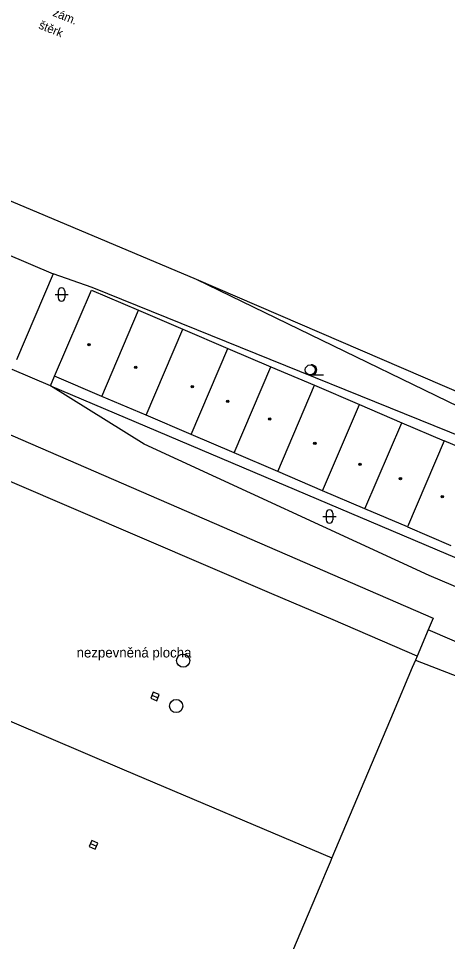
# Model space of a CAD drawing. Extents: x -596024 to -594475, y -1163820 to -1161957.
# Drawn here: x -594771.3 to -594738.8, y -1162292 to -1162222 of the extents above; entities that cross this region are included whole.
import ezdxf

# ---------------------------------------------------------------- set-up
doc = ezdxf.new("R2010")
doc.units = 0
for name, color, linetype in [('Level 10', 7, 'Continuous'), ('Level 11', 7, 'Continuous'), ('Level 14', 7, 'Continuous'), ('Level 27', 7, 'Continuous'), ('Level 36', 7, 'Continuous'), ('Level 39', 7, 'Continuous'), ('Level 40', 7, 'Continuous'), ('Level 42', 7, 'Continuous'), ('Level 5', 7, 'Continuous'), ('Level 6', 7, 'Continuous'), ('Level 7', 7, 'Continuous')]:
    doc.layers.add(name, color=color, linetype=linetype)

msp = doc.modelspace()

# ---------------------------------------------------------------- linework, layer by layer
at = {"layer": 'Level 10'}
for points in [[(-594783.33, -1162270.4), (-594763.33, -1162278.94)], [(-594763.33, -1162278.94), (-594747.59, -1162285.62)]]:
    msp.add_lwpolyline(points, dxfattribs=at)
at = {"layer": 'Level 11'}
for points in [[(-594768.91, -1162249.85), (-594771.8, -1162248.61)], [(-594768.91, -1162249.85), (-594768.6, -1162249.12)], [(-594717.37, -1162273.91), (-594740.22, -1162264.21), (-594761.82, -1162254.28), (-594768.91, -1162249.85)], [(-594768.91, -1162249.85), (-594715.49, -1162272.51)], [(-594752.13, -1162265.61), (-594776.82, -1162255.03)], [(-594747.5, -1162267.57), (-594752.13, -1162265.61)], [(-594741.13, -1162270.32), (-594747.5, -1162267.57)], [(-594718.87, -1162277.56), (-594740.29, -1162268.33)]]:
    msp.add_lwpolyline(points, dxfattribs=at)
at = {"layer": 'Level 14'}
for points in [[(-594765.75, -1162242.39), (-594768.7, -1162241.36)], [(-594729.66, -1162257), (-594765.75, -1162242.39)], [(-594729.32, -1162255.62), (-594757.85, -1162241.8)]]:
    msp.add_lwpolyline(points, dxfattribs=at)
at = {"layer": 'Level 27'}
for p, q in [((-594761.22, -1162273.283), (-594760.76, -1162273.477)), ((-594765.869, -1162284.53), (-594765.411, -1162284.73))]:
    msp.add_line(p, q, dxfattribs=at)
for points in [[(-594761.317, -1162273.513), (-594760.857, -1162273.707), (-594760.663, -1162273.247), (-594761.123, -1162273.053)], [(-594765.969, -1162284.759), (-594765.511, -1162284.959), (-594765.311, -1162284.501), (-594765.769, -1162284.301)]]:
    msp.add_lwpolyline(points, close=True, dxfattribs=at)
for centre in [(-594758.85, -1162270.67), (-594759.39, -1162274.11)]:
    msp.add_circle(centre, 0.5, dxfattribs=at)
at = {"layer": 'Level 36'}
for p, q in [((-594768.566, -1162242.936), (-594767.566, -1162242.936)), ((-594768.316, -1162242.686), (-594768.316, -1162243.186)), ((-594767.816, -1162242.686), (-594767.816, -1162243.186)), ((-594749.23, -1162249.015), (-594748.23, -1162249.015)), ((-594748.266, -1162259.746), (-594747.266, -1162259.746)), ((-594748.016, -1162259.496), (-594748.016, -1162259.996)), ((-594747.516, -1162259.496), (-594747.516, -1162259.996))]:
    msp.add_line(p, q, dxfattribs=at)
msp.add_circle((-594749.23, -1162248.64), 0.375, dxfattribs=at)
for centre, radius, start, end in [((-594768.066, -1162242.686), 0.25, 0, 180), ((-594768.066, -1162243.186), 0.25, 180, 0), ((-594749.105, -1162248.64), 0.375, 260.40593, 99.59407), ((-594747.766, -1162259.496), 0.25, 0, 180), ((-594747.766, -1162259.996), 0.25, 180, 0)]:
    msp.add_arc(centre, radius, start, end, dxfattribs=at)
at = {"layer": 'Level 39'}
for centre, radius in [((-594765.99, -1162246.73), 0.09), ((-594765.99, -1162246.73), 0.0398), ((-594762.45, -1162248.45), 0.09), ((-594762.45, -1162248.45), 0.0398), ((-594758.17, -1162249.92), 0.09), ((-594758.17, -1162249.92), 0.0398), ((-594755.48, -1162251.02), 0.09), ((-594755.48, -1162251.02), 0.0398), ((-594752.3, -1162252.36), 0.09), ((-594752.3, -1162252.36), 0.0398), ((-594748.88, -1162254.2), 0.09), ((-594748.88, -1162254.2), 0.0398), ((-594745.45, -1162255.79), 0.09), ((-594745.45, -1162255.79), 0.0398), ((-594742.39, -1162256.89), 0.09), ((-594742.39, -1162256.89), 0.0398), ((-594739.22, -1162258.24), 0.09), ((-594739.22, -1162258.24), 0.0398)]:
    msp.add_circle(centre, radius, dxfattribs=at)
at = {"layer": 'Level 5'}
for points in [[(-594772.31, -1162239.82), (-594768.7, -1162241.36)], [(-594768.7, -1162241.36), (-594771.49, -1162247.88)], [(-594768.6, -1162249.12), (-594765.81, -1162242.59)], [(-594765.81, -1162242.59), (-594762.23, -1162244.12)], [(-594765.02, -1162250.66), (-594762.23, -1162244.12)], [(-594762.23, -1162244.12), (-594758.87, -1162245.55)], [(-594761.66, -1162252.08), (-594758.87, -1162245.55)], [(-594758.87, -1162245.55), (-594755.47, -1162247.01)], [(-594758.26, -1162253.54), (-594755.47, -1162247.01)], [(-594755.47, -1162247.01), (-594752.21, -1162248.4)], [(-594755, -1162254.93), (-594752.21, -1162248.4)], [(-594752.21, -1162248.4), (-594748.9, -1162249.81)], [(-594765.02, -1162250.66), (-594768.6, -1162249.12)], [(-594751.69, -1162256.34), (-594748.9, -1162249.81)], [(-594748.9, -1162249.81), (-594745.5, -1162251.26)], [(-594761.66, -1162252.08), (-594765.02, -1162250.66)], [(-594748.29, -1162257.8), (-594745.5, -1162251.26)], [(-594745.5, -1162251.26), (-594742.29, -1162252.64)], [(-594758.26, -1162253.54), (-594761.66, -1162252.08)], [(-594745.08, -1162259.17), (-594742.29, -1162252.64)], [(-594742.29, -1162252.64), (-594739.07, -1162254.01)], [(-594755, -1162254.93), (-594758.26, -1162253.54)], [(-594739.07, -1162254.01), (-594741.87, -1162260.54)], [(-594735.79, -1162255.41), (-594739.07, -1162254.01)], [(-594751.69, -1162256.34), (-594755, -1162254.93)], [(-594748.29, -1162257.8), (-594751.69, -1162256.34)], [(-594745.08, -1162259.17), (-594748.29, -1162257.8)], [(-594741.87, -1162260.54), (-594745.08, -1162259.17)], [(-594741.87, -1162260.54), (-594738.58, -1162261.94)], [(-594741.26, -1162270.64), (-594741.5, -1162271.2)], [(-594741.26, -1162270.64), (-594736.89, -1162272.33)], [(-594741.5, -1162271.2), (-594742.94, -1162274.62)], [(-594742.94, -1162274.62), (-594747.59, -1162285.62), (-594747.73, -1162285.95)], [(-594747.73, -1162285.95), (-594748.09, -1162286.81)], [(-594748.09, -1162286.81), (-594748.48, -1162287.73)], [(-594748.48, -1162287.73), (-594750.01, -1162291.36)], [(-594750.01, -1162291.36), (-594760.22, -1162315.51)]]:
    msp.add_lwpolyline(points, dxfattribs=at)
at = {"layer": 'Level 6'}
for points in [[(-594741.5, -1162271.2), (-594742.94, -1162274.62)], [(-594747.73, -1162285.95), (-594748.09, -1162286.81)], [(-594748.48, -1162287.73), (-594750.01, -1162291.36)]]:
    msp.add_lwpolyline(points, dxfattribs=at)
at = {"layer": 'Level 7'}
for points in [[(-594757.85, -1162241.8), (-594778.66, -1162233.02)], [(-594732.82, -1162252.58), (-594757.85, -1162241.8)], [(-594784.94, -1162247.92), (-594739.92, -1162267.46)], [(-594739.92, -1162267.46), (-594740.29, -1162268.33), (-594741.13, -1162270.32), (-594741.26, -1162270.64)]]:
    msp.add_lwpolyline(points, dxfattribs=at)

# ---------------------------------------------------------------- texts
at = {"layer": 'Level 40'}
for s, p in [('zám.', (-594768.79, -1162221.8)), ('štěrk', (-594769.86, -1162222.75))]:
    msp.add_text(s, height=0.65, rotation=338.06, dxfattribs=at).set_placement(p)
at = {"layer": 'Level 42'}
msp.add_text('nezpevněná plocha', height=0.75, dxfattribs=at).set_placement((-594766.93, -1162270.43))

doc.saveas('drawing.dxf')
